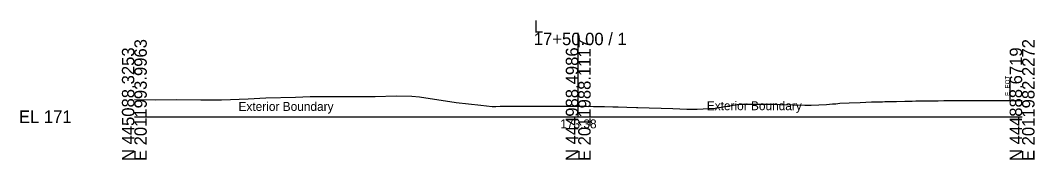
# Model space of a CAD drawing. Extents: x -26 to 4203, y -10 to 9526.
# Drawn here: x -25.7 to 202.8, y 7490.3 to 7521.7 of the extents above; entities that cross this region are included whole.
import ezdxf

# ---------------------------------------------------------------- set-up
doc = ezdxf.new("R2010")
doc.units = 0
for name, color, linetype in [('Default', 7, 'Continuous'), ('Exist Cross Section Cell', 7, 'Continuous'), ('Exist XS Center Line Elevation Label', 7, 'Continuous'), ('Exist XS Ground Line', 7, 'Continuous'), ('Prop XS Label Text', 7, 'Continuous'), ('Scratch_Level_0', 7, 'Continuous')]:
    doc.layers.add(name, color=color, linetype=linetype)

msp = doc.modelspace()

# ---------------------------------------------------------------- linework, layer by layer
at = {"layer": 'Exist Cross Section Cell'}
for p, q in [((100, 7500), (100, 7518.91)), ((0, 7500), (100, 7500)), ((100, 7500), (200, 7500))]:
    msp.add_line(p, q, dxfattribs=at)
at = {"layer": 'Exist XS Ground Line'}
msp.add_lwpolyline([(0, 7503.86), (4.78, 7503.78), (9.58, 7503.84), (14.98, 7503.81), (19.6, 7503.78), (25.63, 7504.04), (29.62, 7504.24), (36.28, 7504.43), (39.64, 7504.52), (46.92, 7504.51), (50.2, 7504.53), (51.54, 7504.52), (54.23, 7504.58), (59, 7504.71), (62.52, 7504.64), (64.25, 7504.44), (72.54, 7503.19), (78.09, 7502.58), (80.65, 7502.32), (81.44, 7502.33), (82.38, 7502.34), (83.4, 7502.35), (85.37, 7502.36), (85.92, 7502.36), (87.73, 7502.36), (88.41, 7502.37), (90.1, 7502.37), (90.93, 7502.37), (91.86, 7502.38), (93.44, 7502.38), (94.54, 7502.38), (95.96, 7502.38), (97.21, 7502.38), (98.45, 7502.39), (99.57, 7502.39), (100, 7502.38), (100.93, 7502.37), (101.92, 7502.35), (103.43, 7502.33), (104.27, 7502.31), (105.94, 7502.29), (107.81, 7502.24), (108.44, 7502.21), (108.99, 7502.21), (110.95, 7502.16), (113.15, 7502.06), (113.45, 7502.04), (115.96, 7502), (118.67, 7501.9), (121.33, 7501.83), (122.88, 7501.75), (124.5, 7501.72), (125.44, 7501.7), (126.18, 7501.7), (126.79, 7501.7), (130.87, 7501.89), (131.31, 7502), (136.26, 7502.8), (136.79, 7502.8), (140.62, 7502.81), (144.31, 7502.79), (145.46, 7502.76), (151.06, 7502.61), (152.51, 7502.56), (155.93, 7502.77), (157.32, 7502.86), (158.02, 7502.9), (158.92, 7503.01), (161.04, 7503.12), (163.55, 7503.21), (166.06, 7503.32), (166.39, 7503.33), (168.56, 7503.38), (169.04, 7503.39), (171.07, 7503.43), (171.71, 7503.44), (173.58, 7503.49), (175.24, 7503.52), (176.09, 7503.54), (177.04, 7503.56), (178.92, 7503.58), (179.41, 7503.59), (181.1, 7503.6), (182.33, 7503.61), (183.59, 7503.61), (184.7, 7503.62), (186.1, 7503.62), (187.06, 7503.62), (188.59, 7503.63), (189.42, 7503.62), (191.1, 7503.63), (191.79, 7503.63), (193.6, 7503.62), (194.08, 7503.62), (195.97, 7503.63), (197.27, 7503.64), (198.6, 7503.64), (200, 7503.64)], dxfattribs=at)
at = {"layer": 'Prop XS Label Text'}
msp.add_line((197.27, 7508.64), (197.27, 7503.64), dxfattribs=at)

# ---------------------------------------------------------------- texts
at = {"layer": 'Default'}
msp.add_text('-', height=0.0001, dxfattribs=at).set_placement((0, 7500))
at = {"layer": 'Exist Cross Section Cell'}
for s, p in [('L', (90, 7518.91)), ('17+50.00 / 1', (90, 7516.11)), ('EL 171', (-26, 7498.6))]:
    msp.add_text(s, height=2.8, dxfattribs=at).set_placement(p)
for s, p in [('E 2011993.9963', (2.8, 7490)), ('E 2011988.1117', (102.8, 7490)), ('E 2011982.2272', (202.8, 7490)), ('N 445088.3253', (0, 7490)), ('N 444988.4986', (100, 7490)), ('N 444888.6719', (200, 7490))]:
    msp.add_text(s, height=2.8, rotation=90, dxfattribs=at).set_placement(p)
at = {"layer": 'Exist XS Center Line Elevation Label'}
msp.add_text('173.38', height=2, dxfattribs=at).set_placement((95.96, 7497.38))
at = {"layer": 'Prop XS Label Text'}
msp.add_text('E. EOT', height=1, rotation=90, dxfattribs=at).set_placement((197.17, 7504.67))
at = {"layer": 'Scratch_Level_0'}
for p in [(23.47, 7501.3), (128.96, 7501.46)]:
    msp.add_text('Exterior Boundary', height=2, dxfattribs=at).set_placement(p)

doc.saveas('drawing.dxf')
